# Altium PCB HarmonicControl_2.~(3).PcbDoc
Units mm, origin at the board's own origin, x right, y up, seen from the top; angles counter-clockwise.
Board outline 77.22 x 40.51 mm, 2 copper layers (Top Layer, Bottom Layer); 18 components, 24 nets, 82 pads, 11 vias.
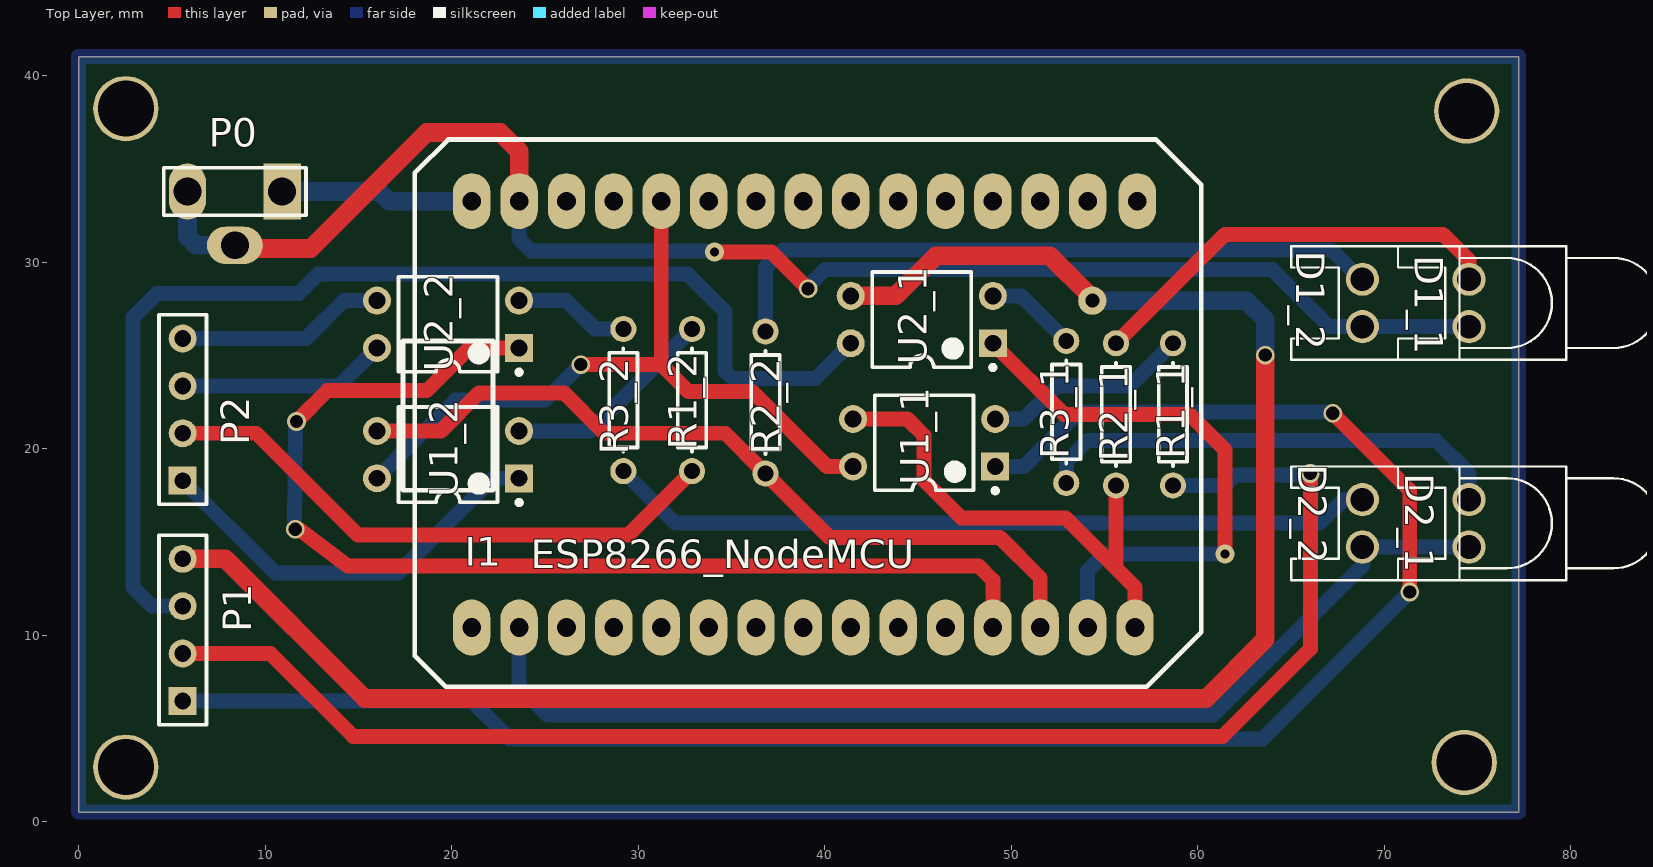
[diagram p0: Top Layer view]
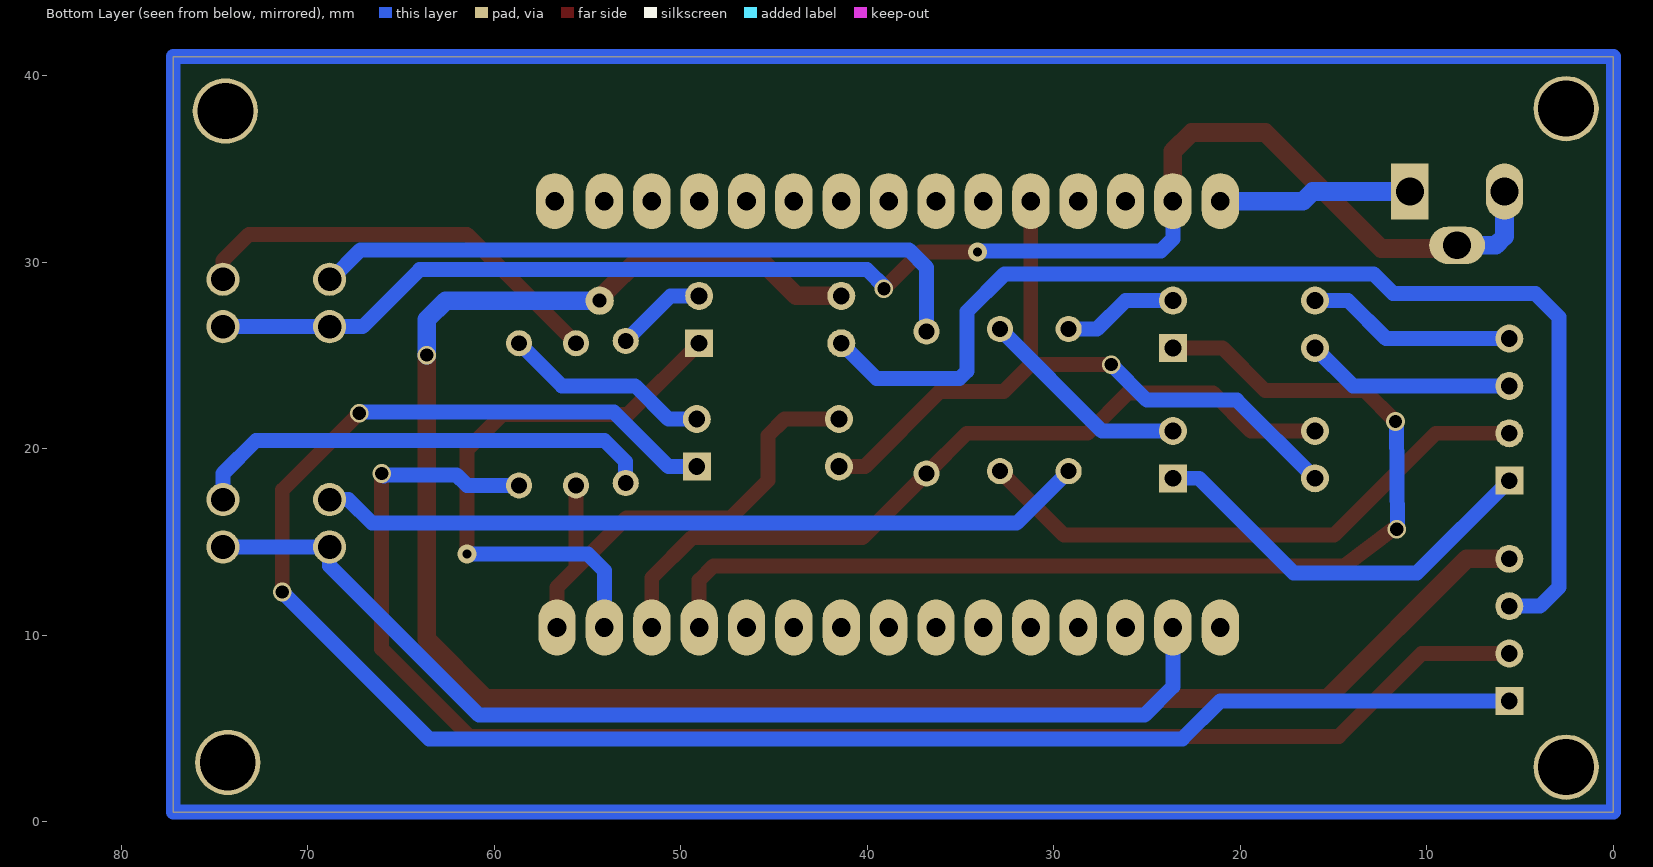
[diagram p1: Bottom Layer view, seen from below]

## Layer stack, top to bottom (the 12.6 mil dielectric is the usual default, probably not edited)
Top Solder: solder mask 0.0102, Solder Resist, Dk 3.5
Top Layer: signal copper 0.0356
Dielectric 1: dielectric 0.32, FR-4, Dk 4.8
Bottom Layer: signal copper 0.0356
Bottom Solder: solder mask 0.0102, Solder Resist, Dk 3.5

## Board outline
0,0.508 77.216,0.508 77.216,41.021 0,41.021

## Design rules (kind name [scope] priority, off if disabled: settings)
Clearance [All] p1: gap=0.254 ignorepadtopadclearanceinfootprint=FALSE except(0: Arc-Hole Track-Hole SMDPad-Hole THPad-Hole Via-Hole Fill-Hole Poly-Hole Region-Hole Text-Hole)
PolygonConnect [All] p1: connectstyle=Relief reliefconductorwidth=0.254 reliefentries=4 polygonreliefangle="90 Angle" airgapwidth=0.254
RoutingVias [All] p1: holewidth=0.711 width=1.27 viastyle="Through Hole" minholewidth=0.711 minwidth=1.27 maxholewidth=0.711 maxwidth=1.27
SolderMaskExpansion [All] p1: expansion=0.102
Width [All] p1: maxlimit=1 minlimit=0.5 preferedwidth=0.8
30 further rules are at their usual default settings.

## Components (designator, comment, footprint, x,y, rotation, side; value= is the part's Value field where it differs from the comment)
D1_1 "LED0" LED-0 74.549,27.806 r90 top
D1_2 "LED0" LED-0 68.834,27.806 r90 top
D2_1 "LED0" LED-0 74.549,15.995 r90 top
D2_2 "LED0" LED-0 68.834,15.995 r90 top
I1 "ESP8266" ESP8266_Node_MCU_V3 21.082,33.267 r270 top
P0 "Jack3.5mm" HDR1X3 10.922,33.782 r180 top
P1 "Cable" HDR1X4 5.588,6.47 r90 top
P2 "Cable" HDR1X4 5.588,18.281 r90 top
R1_1 "Res1" AXIAL-0.3 58.674,21.837 r90 top value=1K
R1_2 "Res1" AXIAL-0.3 32.893,22.599 r90 top value=1K
R2_1 "Res1" AXIAL-0.3 55.626,21.837 r90 top value=1K
R2_2 "Res1" AXIAL-0.3 36.83,22.472 r90 top value=1K
R3_1 "Res1" AXIAL-0.3 52.959,21.964 r90 top value=1K
R3_2 "Res1" AXIAL-0.3 29.21,22.599 r90 top value=1K
U1_1 "InputSignal" DIP-4 45.339,20.313 r180 top
U1_2 "InputSignal" DIP-4 19.812,19.678 r180 top
U2_1 "Output_Control" DIP-4 45.212,26.917 r180 top
U2_2 "Output_Control" DIP-4 19.812,26.663 r180 top

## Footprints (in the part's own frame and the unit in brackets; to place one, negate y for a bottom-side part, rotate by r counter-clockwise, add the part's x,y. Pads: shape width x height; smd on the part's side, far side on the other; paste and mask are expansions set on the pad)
AXIAL-0.3 [mm] "Axial Device, Thru-Hole; 2 Leads; 0.3 in Pin Spacing"
  round 1.4 hole 0.85: 1(-3.81,0) 2(3.81,0)
  silkscreen extent -2.77,-0.76 2.77,0.76
DIP-4 [mm] "DIP; 4 Leads; Row Spacing 7.62 mm; Pitch 2.54 mm"
  rect 1.5x1.5 hole 0.9: 1(-3.81,1.27)
  round 1.5 hole 0.9: 2(-3.81,-1.27) 3(3.81,-1.27) 4(3.81,1.27)
  silkscreen extent -3.94,-2.55 2.65,2.69, body extent -3.15,-2.5 3.15,2.5, height 5.6
ESP8266_Node_MCU_V3 [mm]
  oval 3x2 hole 1 paste+0 mask+0.102: 1(22.86,35.56) 2(22.86,33.02) 3(22.86,30.48) 4(22.86,27.94) 5(22.86,25.4) 6(22.86,22.86) 7(22.86,20.32) 8(22.86,17.78) 9(22.86,15.24) 10(22.86,12.7) 11(22.86,10.16) 12(22.86,7.62) 13(22.86,5.08) 14(22.86,2.54) 15(22.86,0) 16(0,0) 17(0,2.54) 18(0,5.08) 19(0,7.62) 20(0,10.16) 21(0,12.7) 22(0,15.24) 23(0,17.78) 24(0,20.32) 25(0,22.86) 26(0,25.4) 27(0,27.94) 28(0,30.48) 29(0,33.02) 30(0,35.687)
  silkscreen extent -3.3,-3.68 26.04,39.12
HDR1X3 [mm] "Connector; Header; 3 Position"
  rect 2x3 hole 1.5: 1(0,0)
  oval 3x2 hole 1.5: 2(2.54,2.881)
  oval 2x3 hole 1.5: 3(5.08,0)
  silkscreen extent -1.27,-1.27 6.35,1.27
HDR1X4 [mm] "Connector; Header; 4 Position"
  rect 1.5x1.5 hole 0.9: 1(0,0)
  round 1.5 hole 0.9: 2(2.54,0) 3(5.08,0) 4(7.62,0)
  silkscreen extent -1.27,-1.27 8.89,1.27
LED-0 [mil] "LED; 2 Leads"
  round 70 hole 50: 1(50,0) 2(-50,0)
  silkscreen extent -120,-400 120,150

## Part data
D1_1 D1_2 D2_1 D2_2: "Typical INFRARED GaAs LED"
I1: library part ESP8266_Node_MCU_V3
P0: library part "Header 3", "Header, 3-Pin"
P1 P2: library part "Header 4", "Header, 4-Pin"
R1_1 R1_2 R2_1 R2_2 R3_1 R3_2: "Resistor"
U1_1 U1_2 U2_1 U2_2: library part Optoisolator1, "4-Pin Phototransistor Optocoupler"

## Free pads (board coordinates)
  round 1.524 hole 0.762: 2(54.356,27.933)
  round 3.5 hole 3: 12(2.54,38.227) 13(2.54,2.921) 14(74.295,3.175) 15(74.422,38.1)

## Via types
v1: diameter 1, hole 0.711, Top Layer to Bottom Layer, 9 vias
v2: diameter 1, hole 0.5, Top Layer to Bottom Layer, 2 vias

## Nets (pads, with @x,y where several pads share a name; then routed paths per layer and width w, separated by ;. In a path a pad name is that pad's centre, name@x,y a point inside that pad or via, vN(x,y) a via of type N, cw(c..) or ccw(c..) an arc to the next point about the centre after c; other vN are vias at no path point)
GND: D1_1.2 D1_2.2 I1.17 P0.2 P0.3 | length 80.6
  Top Layer w0.8: v2(34.099,30.536) 37.148,30.536 v1(39.116,28.568)
  Top Layer w1: P0.2@9.438,30.727 12.446,30.727 18.669,36.95 22.606,36.95 23.622,35.934 I1.17
  Bottom Layer w0.8: I1.17 23.622,31.235 24.257,30.6 v2@33.909,30.6 ; v1@39.052,28.631 40.012,29.591 64.008,29.591 67.063,26.536 D1_2.2 D1_1.2
  Bottom Layer w1: P0.3 5.842,31.369 6.31,30.901 P0.2
NetD1_1_1: D1_1.1 R2_1.2 | length 22.9
  Top Layer w0.8: R2_1.2 61.468,31.489 73.152,31.489 74.549,30.092 D1_1.1
NetD1_2_1: D1_2.1 R2_2.2 | length 36.5
  Bottom Layer w0.8: R2_2.2 36.83,29.711 37.764,30.645 67.183,30.645 68.752,29.076 D1_2.1
NetD2_1_1: D2_1.1 R3_1.1 | length 25.3
  Bottom Layer w0.8: R3_1.1 52.959,19.297 54.102,20.44 72.771,20.44 74.549,18.662 D2_1.1
NetD2_1_2: D2_1.2 D2_2.2 I1.14 | length 59.1
  Bottom Layer w0.8: I1.14 23.622,7.232 25.139,5.715 60.833,5.715 68.834,13.716 D2_2.2 D2_1.2
NetD2_2_1: D2_2.1 R3_2.1 | length 41.3
  Bottom Layer w0.8: R3_2.1 31.997,16.002 66.555,16.002 67.818,17.265 D2_2.1
NetI1_1: I1.1 R2_1.1 U1_1.3 | length 26.9
  Top Layer w0.8: U1_1.3 44.45,21.583 45.339,20.694 45.339,18.281 47.333,16.287 52.921,16.287 55.626,13.582 ; R2_1.1 55.626,13.582 ; I1.1 56.642,12.566 55.626,13.582
NetI1_2: I1.2 U2_1.1 | length 31.2
  Top Layer w0.8: U2_1.1 52.832,21.837 59.563,21.837 61.468,19.932 v2(61.468,14.351)
  Bottom Layer w0.8: I1.2 54.102,13.462 54.991,14.351 v2(61.468,14.351)
NetI1_3: I1.3 R2_2.1 U1_2.3 | length 43.2
  Top Layer w0.8: U1_2.3 19.431,20.948 21.463,22.98 26.035,22.98 28.194,20.821 34.671,20.821 R2_2.1 40.259,15.233 49.403,15.233 51.562,13.074 I1.3
NetI1_4: I1.4 U2_2.1 | length 60.2
  Top Layer w0.8: v1@11.598,15.647 11.624,15.651 11.811,15.677 14.436,13.709 48.26,13.709 49.022,12.947 I1.4 ; v1(11.684,21.456) 13.335,23.107 18.669,23.107 20.955,25.393 U2_2.1
  Bottom Layer w0.8: v1@11.562,15.678 11.573,15.69 v1@11.632,21.384
  other v1: 11.62,15.677
NetI1_16: I1.16 P0.1 | length 10.4
  Bottom Layer w1: P0.1 16.129,33.782 16.644,33.267 I1.16
NetI1_20: I1.20 U1_1.4 U1_2.4 | length 39.1
  Top Layer w0.8: v1(26.924,24.504) 31.242,24.504 ; I1.20 31.242,24.504 ; U1_1.4 40.132,19.043 36.119,23.056 32.69,23.056 31.242,24.504
  Bottom Layer w0.8: U1_2.4 20.193,22.599 25.019,22.599 v1(26.924,24.504)
NetP1_1: P1.1 U1_1.1 | length 100.2
  Top Layer w0.8: v1@67.437,21.71 71.374,17.773 v1(71.374,12.312)
  Bottom Layer w0.8: P1.1 21.082,6.47 23.114,4.438 63.5,4.438 v1(71.374,12.312) ; U1_1.1 50.673,19.043 53.594,21.964 v1@67.183,21.964
  other v1: 67.246,21.9
NetP1_2: P1.2 R1_1.1 | length 81.1
  Top Layer w0.8: P1.2 10.287,9.01 14.725,4.572 61.348,4.572 66.04,9.264 v1@66.04,18.408
  Bottom Layer w0.8: R1_1.1 61.468,18.027 62.03,18.589 v1@65.848,18.589 ; v1@65.913,18.528 v1@65.848,18.589 ; v1(66.04,18.662) 65.967,18.589 v1@65.848,18.589
NetP1_3: P1.3 U2_1.4 | length 62
  Bottom Layer w0.8: P1.3 3.937,11.55 2.921,12.566 2.921,27.044 4.191,28.314 11.811,28.314 12.852,29.355 32.655,29.355 34.671,27.339 34.671,24.148 35.052,23.767 39.522,23.767 U2_1.4
NetP1_4: P1.4 pad.2 U2_1.3 | length 103.9
  Top Layer w1: P1.4 7.874,14.09 15.36,6.604 60.459,6.604 63.627,9.772 v1(63.627,25.012) ; U2_1.3 43.815,28.187 45.974,30.346 52.07,30.346 pad.2@54.229,28.187
  Bottom Layer w1: v1(54.356,27.933) 62.611,27.933 63.627,26.917 v1(63.627,25.012) ; v1@63.624,25.009 v1@63.624,25.012
NetP2_1: P2.1 U1_2.1 | length 22.2
  Bottom Layer w0.8: P2.1 10.541,13.328 17.145,13.328 22.225,18.408 U1_2.1
NetP2_2: P2.2 R1_2.1 | length 31
  Top Layer w0.8: P2.2 9.525,20.821 14.986,15.36 29.464,15.36 R1_2.1
NetP2_3: P2.3 U2_2.4 | length 11.3
  Bottom Layer w0.8: P2.3 13.97,23.361 U2_2.4
NetP2_4: P2.4 U2_2.3 | length 11.3
  Bottom Layer w0.8: P2.4 12.192,25.901 14.224,27.933 U2_2.3
NetR1_1_2: R1_1.2 U1_1.2 | length 11.2
  Bottom Layer w0.8: U1_1.2 50.673,21.583 52.451,23.361 56.388,23.361 R1_1.2
NetR1_2_2: R1_2.2 U1_2.2 | length 11.5
  Bottom Layer w0.8: U1_2.2 27.432,20.948 R1_2.2
NetR3_1_2: R3_1.2 U2_1.2 | length 4.9
  Bottom Layer w0.8: U2_1.2 50.546,28.187 R3_1.2
NetR3_2_2: R3_2.2 U2_2.2 | length 6.2
  Bottom Layer w0.8: U2_2.2 26.162,27.933 27.686,26.409 R3_2.2
pads on no net: I1.5 I1.6 I1.7 I1.8 I1.9 I1.10 I1.11 I1.12 I1.13 I1.15 I1.18 I1.19 I1.21 I1.22 I1.23 I1.24 I1.25 I1.26 I1.27 I1.28 I1.29 I1.30
copper on no net: | length 235.5
  Bottom Layer w0.8: 0,0.508 77.216,0.508 77.216,41.021 0,41.021 0,0.508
